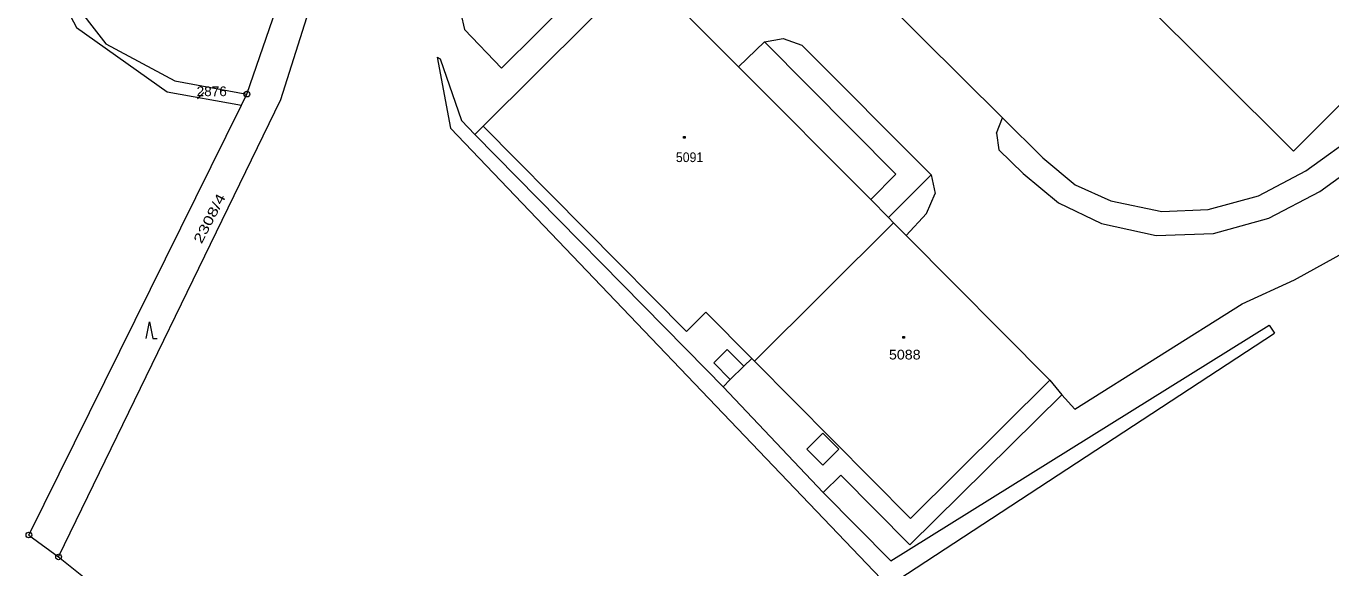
# Model space of a CAD drawing. Extents: x -630464 to -630140, y -1004543 to -1004208.
# Drawn here: x -630453.5 to -630338.9, y -1004476.5 to -1004428.9 of the extents above; entities that cross this region are included whole.
import ezdxf

# ---------------------------------------------------------------- set-up
doc = ezdxf.new("R2010")
doc.units = 0
doc.header["$LTSCALE"] = 0.34
for name, color, linetype, lineweight in [('1', 7, 'Continuous', 13), ('13', 7, 'Continuous', 13), ('2', 7, 'Continuous', 13), ('23', 7, 'Continuous', 13), ('25', 7, 'Continuous', 13), ('28', 7, 'Continuous', 13)]:
    doc.layers.add(name, color=color, linetype=linetype, lineweight=lineweight)
doc.layers.add('14', color=7, linetype='Continuous')
doc.layers.add('15', color=7, linetype='Continuous')

msp = doc.modelspace()

# ---------------------------------------------------------------- linework, layer by layer
at = {"layer": '1'}
for p, q in [((-630450.96, -1004424.73), (-630446.52, -1004430.49)), ((-630449.09, -1004429.04), (-630441.12, -1004434.7)), ((-630390.92, -1004432.51), (-630388.64, -1004430.3)), ((-630441.12, -1004434.7), (-630434.6, -1004435.86)), ((-630414.09, -1004438.44), (-630393.74, -1004459.13)), ((-630374.41, -1004445.4), (-630373.65, -1004443.63)), ((-630376.2, -1004447.31), (-630374.41, -1004445.4)), ((-630392.28, -1004460.61), (-630391.65, -1004459.98)), ((-630375.88, -1004474.48), (-630362.51, -1004461.31)), ((-630453.27, -1004473.63), (-630450.67, -1004475.56)), ((-630450.67, -1004475.56), (-630437.56, -1004485.94))]:
    msp.add_line(p, q, dxfattribs=at)
for points in [[(-630453.27, -1004473.63), (-630434.6, -1004435.86), (-630434.12, -1004434.9), (-630426.2, -1004411.89)], [(-630450.67, -1004475.56), (-630431.15, -1004435.38), (-630427.72, -1004424.53), (-630424.86, -1004425.28), (-630419.62, -1004416.48)], [(-630452.97, -1004420.51), (-630452.61, -1004421.27), (-630451.7, -1004424.09), (-630449.09, -1004429.04)], [(-630414.09, -1004438.44), (-630413.36, -1004437.72), (-630399.48, -1004423.9), (-630390.92, -1004432.51)], [(-630355.83, -1004426.26), (-630342.18, -1004439.92), (-630329.96, -1004427.73), (-630329.26, -1004426.99), (-630328.44, -1004427.8), (-630326.87, -1004429.52), (-630322.01, -1004434.84)], [(-630446.52, -1004430.49), (-630440.46, -1004433.73), (-630434.12, -1004434.9)], [(-630388.64, -1004430.3), (-630386.99, -1004430.01), (-630385.35, -1004430.6), (-630374.01, -1004441.99), (-630373.65, -1004443.63)], [(-630391.65, -1004459.98), (-630390.45, -1004458.79), (-630389.77, -1004458.12), (-630389.53, -1004458.36), (-630377.3, -1004446.21), (-630376.2, -1004447.31), (-630363.57, -1004460.04), (-630362.51, -1004461.31)], [(-630393.74, -1004459.13), (-630392.28, -1004460.61), (-630383.5, -1004469.91)], [(-630383.5, -1004469.91), (-630381.95, -1004468.38), (-630375.88, -1004474.48)]]:
    msp.add_lwpolyline(points, dxfattribs=at)
at = {"layer": '13'}
msp.add_line((-630437.9, -1004434.76), (-630438.45, -1004435.3), dxfattribs=at)
at = {"layer": '2'}
for p, q in [((-630390.36, -1004414.51), (-630367.74, -1004436.99)), ((-630417.48, -1004418.25), (-630415.01, -1004429.22)), ((-630411.76, -1004432.63), (-630401.16, -1004422.1)), ((-630415.01, -1004429.22), (-630411.76, -1004432.63)), ((-630388.64, -1004430.3), (-630377.1, -1004441.93)), ((-630417.41, -1004431.65), (-630416.23, -1004437.89)), ((-630417.41, -1004431.65), (-630417.14, -1004431.79)), ((-630417.14, -1004431.79), (-630415.27, -1004437.23)), ((-630390.92, -1004432.51), (-630379.3, -1004444.17)), ((-630415.27, -1004437.23), (-630414.09, -1004438.44)), ((-630413.36, -1004437.72), (-630395.5, -1004455.74)), ((-630368.25, -1004438.34), (-630367.74, -1004436.99)), ((-630367.74, -1004436.99), (-630364.2, -1004440.51)), ((-630416.23, -1004437.89), (-630377.78, -1004478.11)), ((-630368.25, -1004438.34), (-630368.06, -1004439.8)), ((-630341.08, -1004441.64), (-630336.37, -1004438.25)), ((-630368.06, -1004439.8), (-630365.91, -1004441.88)), ((-630339.86, -1004443.44), (-630334.95, -1004439.88)), ((-630364.2, -1004440.51), (-630361.35, -1004442.87)), ((-630379.3, -1004444.17), (-630377.1, -1004441.93)), ((-630377.74, -1004445.75), (-630374.01, -1004441.99)), ((-630365.91, -1004441.88), (-630362.81, -1004444.46)), ((-630345.24, -1004443.83), (-630341.08, -1004441.64)), ((-630361.35, -1004442.87), (-630358.22, -1004444.26)), ((-630344.33, -1004445.79), (-630339.86, -1004443.44)), ((-630379.3, -1004444.17), (-630377.74, -1004445.75)), ((-630362.81, -1004444.46), (-630359.04, -1004446.26)), ((-630358.22, -1004444.26), (-630353.74, -1004445.21)), ((-630349.66, -1004445.03), (-630345.24, -1004443.83)), ((-630377.74, -1004445.75), (-630377.3, -1004446.21)), ((-630353.74, -1004445.21), (-630349.66, -1004445.03)), ((-630349.19, -1004447.13), (-630344.33, -1004445.79)), ((-630359.04, -1004446.26), (-630354.22, -1004447.33)), ((-630354.22, -1004447.33), (-630349.19, -1004447.13)), ((-630342.07, -1004451.2), (-630336.72, -1004448.26)), ((-630346.68, -1004453.32), (-630342.07, -1004451.2)), ((-630361.37, -1004462.57), (-630346.68, -1004453.32)), ((-630395.5, -1004455.74), (-630393.79, -1004454.06)), ((-630393.79, -1004454.06), (-630389.77, -1004458.12)), ((-630377.78, -1004478.11), (-630343.84, -1004455.89)), ((-630377.55, -1004475.9), (-630344.3, -1004455.19)), ((-630344.3, -1004455.19), (-630343.84, -1004455.89)), ((-630393.11, -1004458.51), (-630391.91, -1004457.32)), ((-630391.91, -1004457.32), (-630390.45, -1004458.79)), ((-630389.53, -1004458.36), (-630375.83, -1004472.18)), ((-630393.11, -1004458.51), (-630391.65, -1004459.98)), ((-630375.83, -1004472.18), (-630363.57, -1004460.04)), ((-630362.51, -1004461.31), (-630361.37, -1004462.57)), ((-630384.92, -1004466.08), (-630383.52, -1004464.69)), ((-630383.52, -1004464.69), (-630382.12, -1004466.1)), ((-630384.92, -1004466.08), (-630383.52, -1004467.49)), ((-630383.52, -1004467.49), (-630382.12, -1004466.1)), ((-630383.5, -1004469.91), (-630377.55, -1004475.9))]:
    msp.add_line(p, q, dxfattribs=at)
at = {"layer": '23'}
msp.add_lwpolyline([(-630442.966, -1004456.38), (-630442.67, -1004454.9), (-630442.374, -1004456.38), (-630442.004, -1004456.38)], dxfattribs=at)
at = {"layer": '25'}
for points in [[(-630395.77, -1004438.63), (-630395.62, -1004438.63), (-630395.62, -1004438.78), (-630395.77, -1004438.78)], [(-630376.5, -1004456.18), (-630376.35, -1004456.18), (-630376.35, -1004456.33), (-630376.5, -1004456.33)]]:
    msp.add_lwpolyline(points, close=True, dxfattribs=at)
at = {"layer": '28'}
for centre, radius in [((-630434.12, -1004434.9), 0.25), ((-630434.12, -1004434.9), 0.005), ((-630453.27, -1004473.63), 0.25), ((-630453.27, -1004473.63), 0.005), ((-630450.67, -1004475.56), 0.25), ((-630450.67, -1004475.56), 0.005)]:
    msp.add_circle(centre, radius, dxfattribs=at)

# ---------------------------------------------------------------- texts
at = {"layer": '14', "width": 1.05}
msp.add_text('2876', height=0.85, dxfattribs=at).set_placement((-630438.54, -1004435.08))
at = {"layer": '14', "width": 1.35}
msp.add_text('2308/4', height=0.85, rotation=62.754, dxfattribs=at).set_placement((-630438.104, -1004448.102))
at = {"layer": '15'}
for s, width, p in [('5091', 0.95, (-630396.43, -1004440.87)), ('5088', 1.1, (-630377.71, -1004458.21))]:
    msp.add_text(s, height=0.85, dxfattribs=dict(at, width=width)).set_placement(p)

doc.saveas('drawing.dxf')
